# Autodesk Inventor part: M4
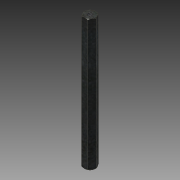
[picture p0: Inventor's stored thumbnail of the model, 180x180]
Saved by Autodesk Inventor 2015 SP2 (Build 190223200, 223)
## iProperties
Created: 2012-08
Part Number: M4
Material: Stahl
Document SubType Name: Modeling
Designer: rYan
Mass: 22.7967 g
Surface Area: 29.895 cm^2
Volume: 2.90403 cm^3
Density: 7.85 g/cm^3
Appearance: Stahl - Guss
Author: rYan
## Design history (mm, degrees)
derived "Abstandsbolzen Typ A.ipt"
feature "Volumenkörper1::Abstandsbolzen Typ A.ipt"
tag "Bezeichnung1"
node "Volumenkörper1"
other parameters: "SW" = 7, "L" = 85, "d2" = 0, "d16" = 45 deg
